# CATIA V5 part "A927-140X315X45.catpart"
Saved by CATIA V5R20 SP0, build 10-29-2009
Part number: A927-140X315X45
Source: Unknown
Property "A": "90.000"
Property "ARTICLENO": "A927-140X315X45"
Property "BOMINFO": "A927-140X315X45"
Property "CODE": "A927-140X315X45"
Property "CREATOR": "CADENAS GmbH"
Property "D": "22.000"
Property "D1": "33.000"
Property "F": "36.000"
Property "FORM": "B"
Property "L": "315.000"
Property "L1": "150.000"
Property "L2": "40.000"
Property "L3": "80.000"
Property "LINA": "A927-140X315X45"
Property "NB": "A927-140X315X45"
Property "NBSYN": "$CODE."
Property "NN": "A927"
Property "NT": "VDI 3387 Removable Die Heels, steel and self-lubricating"
Property "R": "31.500"
Property "S": "45.000"
Property "SUPPLIER": "CF"
Property "T": "25.500"
Property "W": "140.000"
Bounding box of the stored display mesh (mm): x -70 to 70, y 0 to 315, z -45 to 0
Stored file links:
  C:\Users\borellobunino\Desktop\3D X SITO CF\A927\GSB_OILLESS_G2290514031545\CATIAV5\A927-140X315X45.catpart
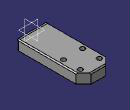
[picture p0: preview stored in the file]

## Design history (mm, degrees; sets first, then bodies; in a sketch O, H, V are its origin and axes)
Body1 "Geometry.1" (main body)
  Solid1 "A927-140X315X45.catpart": solid without history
